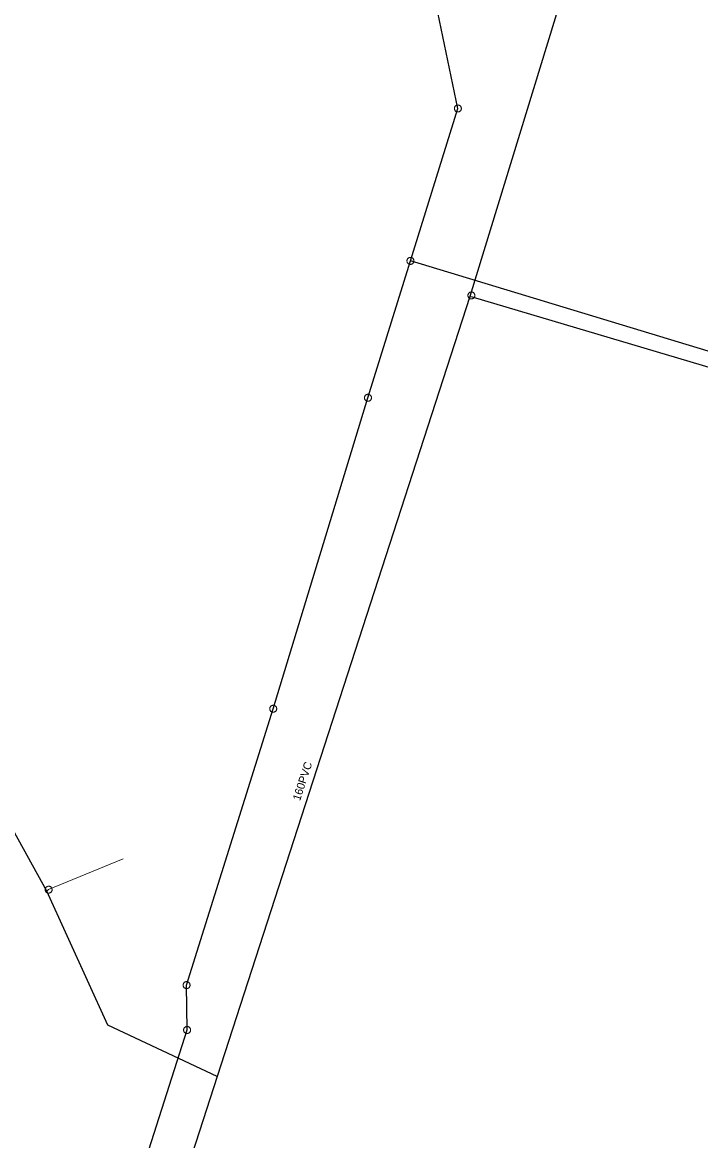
# Model space of a CAD drawing. Extents: x -741806 to -738704, y -1059275 to -1055387.
# Drawn here: x -740463.8 to -740379, y -1057368.6 to -1057228.9 of the extents above; entities that cross this region are included whole.
import ezdxf

# ---------------------------------------------------------------- set-up
doc = ezdxf.new("R2010")
doc.units = 0
doc.header["$LTSCALE"] = 0.4
for name, color, linetype, lineweight in [('2', 7, 'Continuous', 25), ('21', 7, 'Continuous', 13), ('3', 7, 'Continuous', 13), ('51', 7, 'Continuous', 13), ('52', 7, 'Continuous', 25)]:
    doc.layers.add(name, color=color, linetype=linetype, lineweight=lineweight)
doc.layers.add('53', color=7, linetype='Continuous')

msp = doc.modelspace()

# ---------------------------------------------------------------- linework, layer by layer
at = {"layer": '2'}
for points in [[(-740415.289, -1057258.669), (-740409.359, -1057239.62), (-740413.129, -1057221.58), (-740396.239, -1057164.08)], [(-740463.206, -1057418.767), (-740456.879, -1057397.58), (-740443.219, -1057354.797), (-740443.287, -1057349.189), (-740432.452, -1057314.649), (-740420.603, -1057275.773), (-740415.289, -1057258.669)], [(-740318.07, -1057288.6), (-740320.633, -1057287.799), (-740367.329, -1057273.19), (-740415.289, -1057258.669)]]:
    msp.add_lwpolyline(points, dxfattribs=at)
at = {"layer": '21'}
msp.add_lwpolyline([(-740460.763, -1057337.442), (-740460.535, -1057337.252), (-740451.201, -1057333.411)], dxfattribs=at)
at = {"layer": '3'}
for points in [[(-740409.228, -1057239.201), (-740409.272, -1057239.191), (-740409.317, -1057239.184), (-740409.363, -1057239.182), (-740409.408, -1057239.185), (-740409.454, -1057239.193), (-740409.498, -1057239.205), (-740409.54, -1057239.223), (-740409.581, -1057239.243), (-740409.619, -1057239.269), (-740409.654, -1057239.298), (-740409.686, -1057239.331), (-740409.715, -1057239.367), (-740409.739, -1057239.406), (-740409.76, -1057239.446), (-740409.775, -1057239.49), (-740409.787, -1057239.534), (-740409.793, -1057239.58), (-740409.795, -1057239.625), (-740409.792, -1057239.671), (-740409.784, -1057239.716), (-740409.771, -1057239.76), (-740409.755, -1057239.802), (-740409.733, -1057239.843), (-740409.709, -1057239.881), (-740409.679, -1057239.917), (-740409.646, -1057239.948), (-740409.611, -1057239.977), (-740409.571, -1057240.002), (-740409.53, -1057240.022), (-740409.487, -1057240.037), (-740409.443, -1057240.049), (-740409.398, -1057240.055), (-740409.352, -1057240.057), (-740409.306, -1057240.054), (-740409.262, -1057240.047), (-740409.217, -1057240.034), (-740409.175, -1057240.017), (-740409.134, -1057239.995), (-740409.096, -1057239.97), (-740409.061, -1057239.941), (-740409.029, -1057239.908), (-740409, -1057239.872), (-740408.975, -1057239.834), (-740408.955, -1057239.793), (-740408.94, -1057239.75), (-740408.928, -1057239.705), (-740408.921, -1057239.66), (-740408.92, -1057239.615), (-740408.923, -1057239.569), (-740408.931, -1057239.523), (-740408.944, -1057239.479), (-740408.96, -1057239.437), (-740408.982, -1057239.396), (-740409.006, -1057239.358), (-740409.036, -1057239.323), (-740409.069, -1057239.291), (-740409.105, -1057239.263), (-740409.144, -1057239.238), (-740409.185, -1057239.218), (-740409.227, -1057239.202)], [(-740415.158, -1057258.25), (-740415.202, -1057258.24), (-740415.247, -1057258.233), (-740415.293, -1057258.231), (-740415.338, -1057258.234), (-740415.384, -1057258.242), (-740415.428, -1057258.254), (-740415.47, -1057258.272), (-740415.511, -1057258.292), (-740415.549, -1057258.318), (-740415.584, -1057258.347), (-740415.616, -1057258.38), (-740415.645, -1057258.416), (-740415.669, -1057258.455), (-740415.69, -1057258.495), (-740415.705, -1057258.539), (-740415.717, -1057258.583), (-740415.723, -1057258.629), (-740415.725, -1057258.674), (-740415.722, -1057258.72), (-740415.714, -1057258.765), (-740415.701, -1057258.809), (-740415.685, -1057258.851), (-740415.663, -1057258.892), (-740415.639, -1057258.93), (-740415.609, -1057258.966), (-740415.576, -1057258.997), (-740415.541, -1057259.026), (-740415.501, -1057259.051), (-740415.46, -1057259.071), (-740415.417, -1057259.086), (-740415.373, -1057259.098), (-740415.328, -1057259.104), (-740415.282, -1057259.106), (-740415.236, -1057259.103), (-740415.192, -1057259.096), (-740415.147, -1057259.083), (-740415.105, -1057259.066), (-740415.064, -1057259.044), (-740415.026, -1057259.019), (-740414.991, -1057258.99), (-740414.959, -1057258.957), (-740414.93, -1057258.921), (-740414.905, -1057258.883), (-740414.885, -1057258.842), (-740414.87, -1057258.799), (-740414.858, -1057258.754), (-740414.851, -1057258.709), (-740414.85, -1057258.664), (-740414.853, -1057258.618), (-740414.861, -1057258.572), (-740414.874, -1057258.528), (-740414.89, -1057258.486), (-740414.912, -1057258.445), (-740414.936, -1057258.407), (-740414.966, -1057258.372), (-740414.999, -1057258.34), (-740415.035, -1057258.312), (-740415.074, -1057258.287), (-740415.115, -1057258.267), (-740415.157, -1057258.251)], [(-740420.474, -1057275.354), (-740420.518, -1057275.343), (-740420.563, -1057275.337), (-740420.61, -1057275.335), (-740420.655, -1057275.338), (-740420.7, -1057275.347), (-740420.745, -1057275.359), (-740420.787, -1057275.377), (-740420.827, -1057275.398), (-740420.865, -1057275.424), (-740420.9, -1057275.453), (-740420.932, -1057275.486), (-740420.961, -1057275.522), (-740420.984, -1057275.561), (-740421.005, -1057275.602), (-740421.02, -1057275.645), (-740421.032, -1057275.69), (-740421.037, -1057275.735), (-740421.039, -1057275.78), (-740421.036, -1057275.827), (-740421.027, -1057275.872), (-740421.015, -1057275.916), (-740420.998, -1057275.957), (-740420.976, -1057275.998), (-740420.951, -1057276.036), (-740420.921, -1057276.072), (-740420.888, -1057276.103), (-740420.852, -1057276.131), (-740420.813, -1057276.156), (-740420.772, -1057276.176), (-740420.728, -1057276.191), (-740420.685, -1057276.202), (-740420.64, -1057276.209), (-740420.593, -1057276.21), (-740420.547, -1057276.206), (-740420.503, -1057276.199), (-740420.458, -1057276.186), (-740420.417, -1057276.169), (-740420.375, -1057276.147), (-740420.338, -1057276.122), (-740420.303, -1057276.093), (-740420.271, -1057276.06), (-740420.242, -1057276.023), (-740420.218, -1057275.985), (-740420.198, -1057275.944), (-740420.183, -1057275.9), (-740420.172, -1057275.856), (-740420.165, -1057275.811), (-740420.164, -1057275.765), (-740420.168, -1057275.719), (-740420.176, -1057275.674), (-740420.188, -1057275.63), (-740420.205, -1057275.587), (-740420.227, -1057275.547), (-740420.252, -1057275.509), (-740420.282, -1057275.474), (-740420.315, -1057275.442), (-740420.351, -1057275.414), (-740420.39, -1057275.39), (-740420.431, -1057275.37), (-740420.473, -1057275.354)], [(-740432.32, -1057314.231), (-740432.364, -1057314.22), (-740432.409, -1057314.213), (-740432.455, -1057314.211), (-740432.5, -1057314.214), (-740432.546, -1057314.222), (-740432.59, -1057314.234), (-740432.632, -1057314.251), (-740432.673, -1057314.272), (-740432.711, -1057314.298), (-740432.746, -1057314.327), (-740432.778, -1057314.359), (-740432.808, -1057314.395), (-740432.831, -1057314.434), (-740432.852, -1057314.475), (-740432.868, -1057314.518), (-740432.88, -1057314.562), (-740432.886, -1057314.608), (-740432.888, -1057314.653), (-740432.885, -1057314.699), (-740432.877, -1057314.744), (-740432.865, -1057314.788), (-740432.849, -1057314.83), (-740432.827, -1057314.871), (-740432.802, -1057314.909), (-740432.772, -1057314.945), (-740432.739, -1057314.976), (-740432.704, -1057315.005), (-740432.665, -1057315.03), (-740432.624, -1057315.05), (-740432.581, -1057315.066), (-740432.537, -1057315.077), (-740432.492, -1057315.084), (-740432.446, -1057315.086), (-740432.4, -1057315.083), (-740432.356, -1057315.076), (-740432.311, -1057315.064), (-740432.269, -1057315.046), (-740432.227, -1057315.025), (-740432.19, -1057315), (-740432.155, -1057314.971), (-740432.123, -1057314.938), (-740432.094, -1057314.902), (-740432.069, -1057314.864), (-740432.049, -1057314.823), (-740432.033, -1057314.78), (-740432.021, -1057314.735), (-740432.014, -1057314.69), (-740432.013, -1057314.645), (-740432.016, -1057314.599), (-740432.024, -1057314.553), (-740432.036, -1057314.509), (-740432.052, -1057314.467), (-740432.074, -1057314.426), (-740432.099, -1057314.388), (-740432.129, -1057314.353), (-740432.161, -1057314.32), (-740432.197, -1057314.292), (-740432.236, -1057314.268), (-740432.277, -1057314.247), (-740432.319, -1057314.231)], [(-740443.291, -1057348.751), (-740443.336, -1057348.754), (-740443.381, -1057348.762), (-740443.426, -1057348.774), (-740443.468, -1057348.791), (-740443.509, -1057348.812), (-740443.547, -1057348.838), (-740443.582, -1057348.867), (-740443.615, -1057348.899), (-740443.642, -1057348.936), (-740443.667, -1057348.974), (-740443.687, -1057349.015), (-740443.704, -1057349.059), (-740443.714, -1057349.103), (-740443.722, -1057349.148), (-740443.723, -1057349.194), (-740443.72, -1057349.24), (-740443.712, -1057349.285), (-740443.7, -1057349.329), (-740443.683, -1057349.371), (-740443.661, -1057349.412), (-740443.636, -1057349.45), (-740443.607, -1057349.484), (-740443.574, -1057349.517), (-740443.539, -1057349.546), (-740443.499, -1057349.57), (-740443.458, -1057349.59), (-740443.416, -1057349.606), (-740443.371, -1057349.618), (-740443.326, -1057349.624), (-740443.28, -1057349.625), (-740443.235, -1057349.623), (-740443.19, -1057349.615), (-740443.145, -1057349.603), (-740443.102, -1057349.585), (-740443.062, -1057349.565), (-740443.024, -1057349.539), (-740442.989, -1057349.51), (-740442.956, -1057349.477), (-740442.929, -1057349.441), (-740442.904, -1057349.403), (-740442.884, -1057349.362), (-740442.867, -1057349.318), (-740442.856, -1057349.274), (-740442.849, -1057349.229), (-740442.848, -1057349.183), (-740442.851, -1057349.137), (-740442.858, -1057349.092), (-740442.871, -1057349.048), (-740442.888, -1057349.006), (-740442.91, -1057348.965), (-740442.935, -1057348.927), (-740442.964, -1057348.892), (-740442.997, -1057348.86), (-740443.032, -1057348.831), (-740443.072, -1057348.807), (-740443.113, -1057348.786), (-740443.155, -1057348.771), (-740443.2, -1057348.759), (-740443.245, -1057348.753), (-740443.29, -1057348.751)], [(-740443.085, -1057354.379), (-740443.129, -1057354.369), (-740443.174, -1057354.362), (-740443.22, -1057354.359), (-740443.265, -1057354.362), (-740443.31, -1057354.369), (-740443.355, -1057354.381), (-740443.397, -1057354.398), (-740443.439, -1057354.419), (-740443.476, -1057354.444), (-740443.512, -1057354.473), (-740443.544, -1057354.506), (-740443.573, -1057354.542), (-740443.597, -1057354.58), (-740443.618, -1057354.621), (-740443.634, -1057354.664), (-740443.646, -1057354.708), (-740443.652, -1057354.753), (-740443.655, -1057354.799), (-740443.652, -1057354.845), (-740443.645, -1057354.89), (-740443.632, -1057354.934), (-740443.616, -1057354.976), (-740443.595, -1057355.017), (-740443.571, -1057355.056), (-740443.541, -1057355.091), (-740443.508, -1057355.123), (-740443.473, -1057355.152), (-740443.434, -1057355.177), (-740443.393, -1057355.197), (-740443.35, -1057355.213), (-740443.307, -1057355.225), (-740443.262, -1057355.232), (-740443.215, -1057355.234), (-740443.169, -1057355.231), (-740443.125, -1057355.224), (-740443.08, -1057355.212), (-740443.038, -1057355.195), (-740442.996, -1057355.174), (-740442.959, -1057355.149), (-740442.924, -1057355.121), (-740442.891, -1057355.088), (-740442.862, -1057355.052), (-740442.837, -1057355.014), (-740442.817, -1057354.973), (-740442.801, -1057354.93), (-740442.789, -1057354.885), (-740442.782, -1057354.84), (-740442.78, -1057354.795), (-740442.783, -1057354.749), (-740442.79, -1057354.703), (-740442.803, -1057354.659), (-740442.818, -1057354.617), (-740442.84, -1057354.576), (-740442.865, -1057354.538), (-740442.894, -1057354.502), (-740442.927, -1057354.47), (-740442.962, -1057354.442), (-740443.001, -1057354.417), (-740443.042, -1057354.396), (-740443.084, -1057354.38)]]:
    msp.add_lwpolyline(points, dxfattribs=at)
at = {"layer": '51'}
for points in [[(-740407.232, -1057262.985), (-740407.233, -1057262.94), (-740407.241, -1057262.895), (-740407.253, -1057262.85), (-740407.269, -1057262.808), (-740407.29, -1057262.767), (-740407.315, -1057262.728), (-740407.344, -1057262.693), (-740407.376, -1057262.66), (-740407.412, -1057262.632), (-740407.45, -1057262.607), (-740407.491, -1057262.586), (-740407.534, -1057262.569), (-740407.578, -1057262.557), (-740407.623, -1057262.55), (-740407.669, -1057262.548), (-740407.715, -1057262.55), (-740407.76, -1057262.557), (-740407.804, -1057262.569), (-740407.847, -1057262.586), (-740407.888, -1057262.607), (-740407.926, -1057262.632), (-740407.962, -1057262.66), (-740407.994, -1057262.693), (-740408.023, -1057262.728), (-740408.048, -1057262.767), (-740408.069, -1057262.808), (-740408.085, -1057262.85), (-740408.097, -1057262.895), (-740408.104, -1057262.94), (-740408.107, -1057262.986), (-740408.104, -1057263.031), (-740408.097, -1057263.076), (-740408.085, -1057263.121), (-740408.069, -1057263.163), (-740408.048, -1057263.204), (-740408.023, -1057263.243), (-740407.994, -1057263.278), (-740407.962, -1057263.311), (-740407.926, -1057263.339), (-740407.888, -1057263.364), (-740407.847, -1057263.385), (-740407.804, -1057263.402), (-740407.76, -1057263.413), (-740407.715, -1057263.421), (-740407.669, -1057263.423), (-740407.623, -1057263.421), (-740407.578, -1057263.413), (-740407.534, -1057263.402), (-740407.491, -1057263.385), (-740407.45, -1057263.364), (-740407.412, -1057263.339), (-740407.376, -1057263.311), (-740407.344, -1057263.278), (-740407.315, -1057263.243), (-740407.29, -1057263.204), (-740407.269, -1057263.163), (-740407.253, -1057263.121), (-740407.241, -1057263.076), (-740407.233, -1057263.031), (-740407.232, -1057262.986)], [(-740460.198, -1057336.972), (-740460.229, -1057336.939), (-740460.263, -1057336.909), (-740460.301, -1057336.882), (-740460.34, -1057336.86), (-740460.383, -1057336.842), (-740460.427, -1057336.828), (-740460.471, -1057336.82), (-740460.517, -1057336.815), (-740460.563, -1057336.816), (-740460.608, -1057336.821), (-740460.653, -1057336.831), (-740460.697, -1057336.846), (-740460.738, -1057336.865), (-740460.777, -1057336.888), (-740460.814, -1057336.916), (-740460.848, -1057336.947), (-740460.878, -1057336.981), (-740460.904, -1057337.019), (-740460.926, -1057337.059), (-740460.944, -1057337.102), (-740460.958, -1057337.145), (-740460.967, -1057337.19), (-740460.971, -1057337.236), (-740460.971, -1057337.281), (-740460.965, -1057337.327), (-740460.955, -1057337.372), (-740460.94, -1057337.414), (-740460.921, -1057337.457), (-740460.897, -1057337.496), (-740460.87, -1057337.533), (-740460.839, -1057337.566), (-740460.805, -1057337.596), (-740460.767, -1057337.623), (-740460.728, -1057337.645), (-740460.685, -1057337.663), (-740460.641, -1057337.677), (-740460.596, -1057337.685), (-740460.551, -1057337.69), (-740460.505, -1057337.688), (-740460.46, -1057337.683), (-740460.415, -1057337.673), (-740460.371, -1057337.659), (-740460.33, -1057337.639), (-740460.29, -1057337.616), (-740460.254, -1057337.588), (-740460.22, -1057337.557), (-740460.19, -1057337.522), (-740460.164, -1057337.486), (-740460.141, -1057337.445), (-740460.123, -1057337.403), (-740460.11, -1057337.359), (-740460.1, -1057337.315), (-740460.097, -1057337.269), (-740460.097, -1057337.223), (-740460.103, -1057337.177), (-740460.113, -1057337.133), (-740460.128, -1057337.09), (-740460.147, -1057337.048), (-740460.171, -1057337.009), (-740460.198, -1057336.973)]]:
    msp.add_lwpolyline(points, dxfattribs=at)
at = {"layer": '52'}
msp.add_line((-740379.353, -1057170.263), (-740407.857, -1057263.098), dxfattribs=at)
for points in [[(-740407.857, -1057263.098), (-740439.467, -1057360.607), (-740447.059, -1057384.081), (-740447.248, -1057384.679), (-740452.412, -1057401.031), (-740457.603, -1057418.83), (-740467.015, -1057450.047), (-740468.397, -1057454.838), (-740469.89, -1057459.936), (-740472.616, -1057468.997), (-740478.407, -1057487.088), (-740480.659, -1057495.081), (-740486.488, -1057512.648), (-740486.78, -1057514.456), (-740493.754, -1057537.497), (-740495.864, -1057543.049), (-740500.778, -1057560.762), (-740501.975, -1057565.431)], [(-740407.857, -1057263.098), (-740407.578, -1057263.179), (-740374.585, -1057272.968), (-740371.978, -1057273.828), (-740369.046, -1057274.632), (-740326.969, -1057287.04), (-740319.489, -1057289.497)], [(-740439.467, -1057360.607), (-740453.131, -1057354.175), (-740460.763, -1057337.442), (-740473.807, -1057313.848)]]:
    msp.add_lwpolyline(points, dxfattribs=at)

# ---------------------------------------------------------------- texts
at = {"layer": '53'}
msp.add_text('160PVC', height=1, rotation=72, dxfattribs=at).set_placement((-740429.095, -1057326.212))

doc.saveas('drawing.dxf')
